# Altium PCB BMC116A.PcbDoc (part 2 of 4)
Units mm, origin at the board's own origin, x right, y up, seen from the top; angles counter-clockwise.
Board outline 154.94 x 104.14 mm, 6 copper layers (Top Layer, Signal Layer 1, Signal Layer 2, Signal Layer 3, Signal Layer 4, Bottom Layer), stack 1.56 mm thick; 252 components, 114 nets, 652 pads, 2530 vias.
Unrouted connection lines stored in the file: 13.
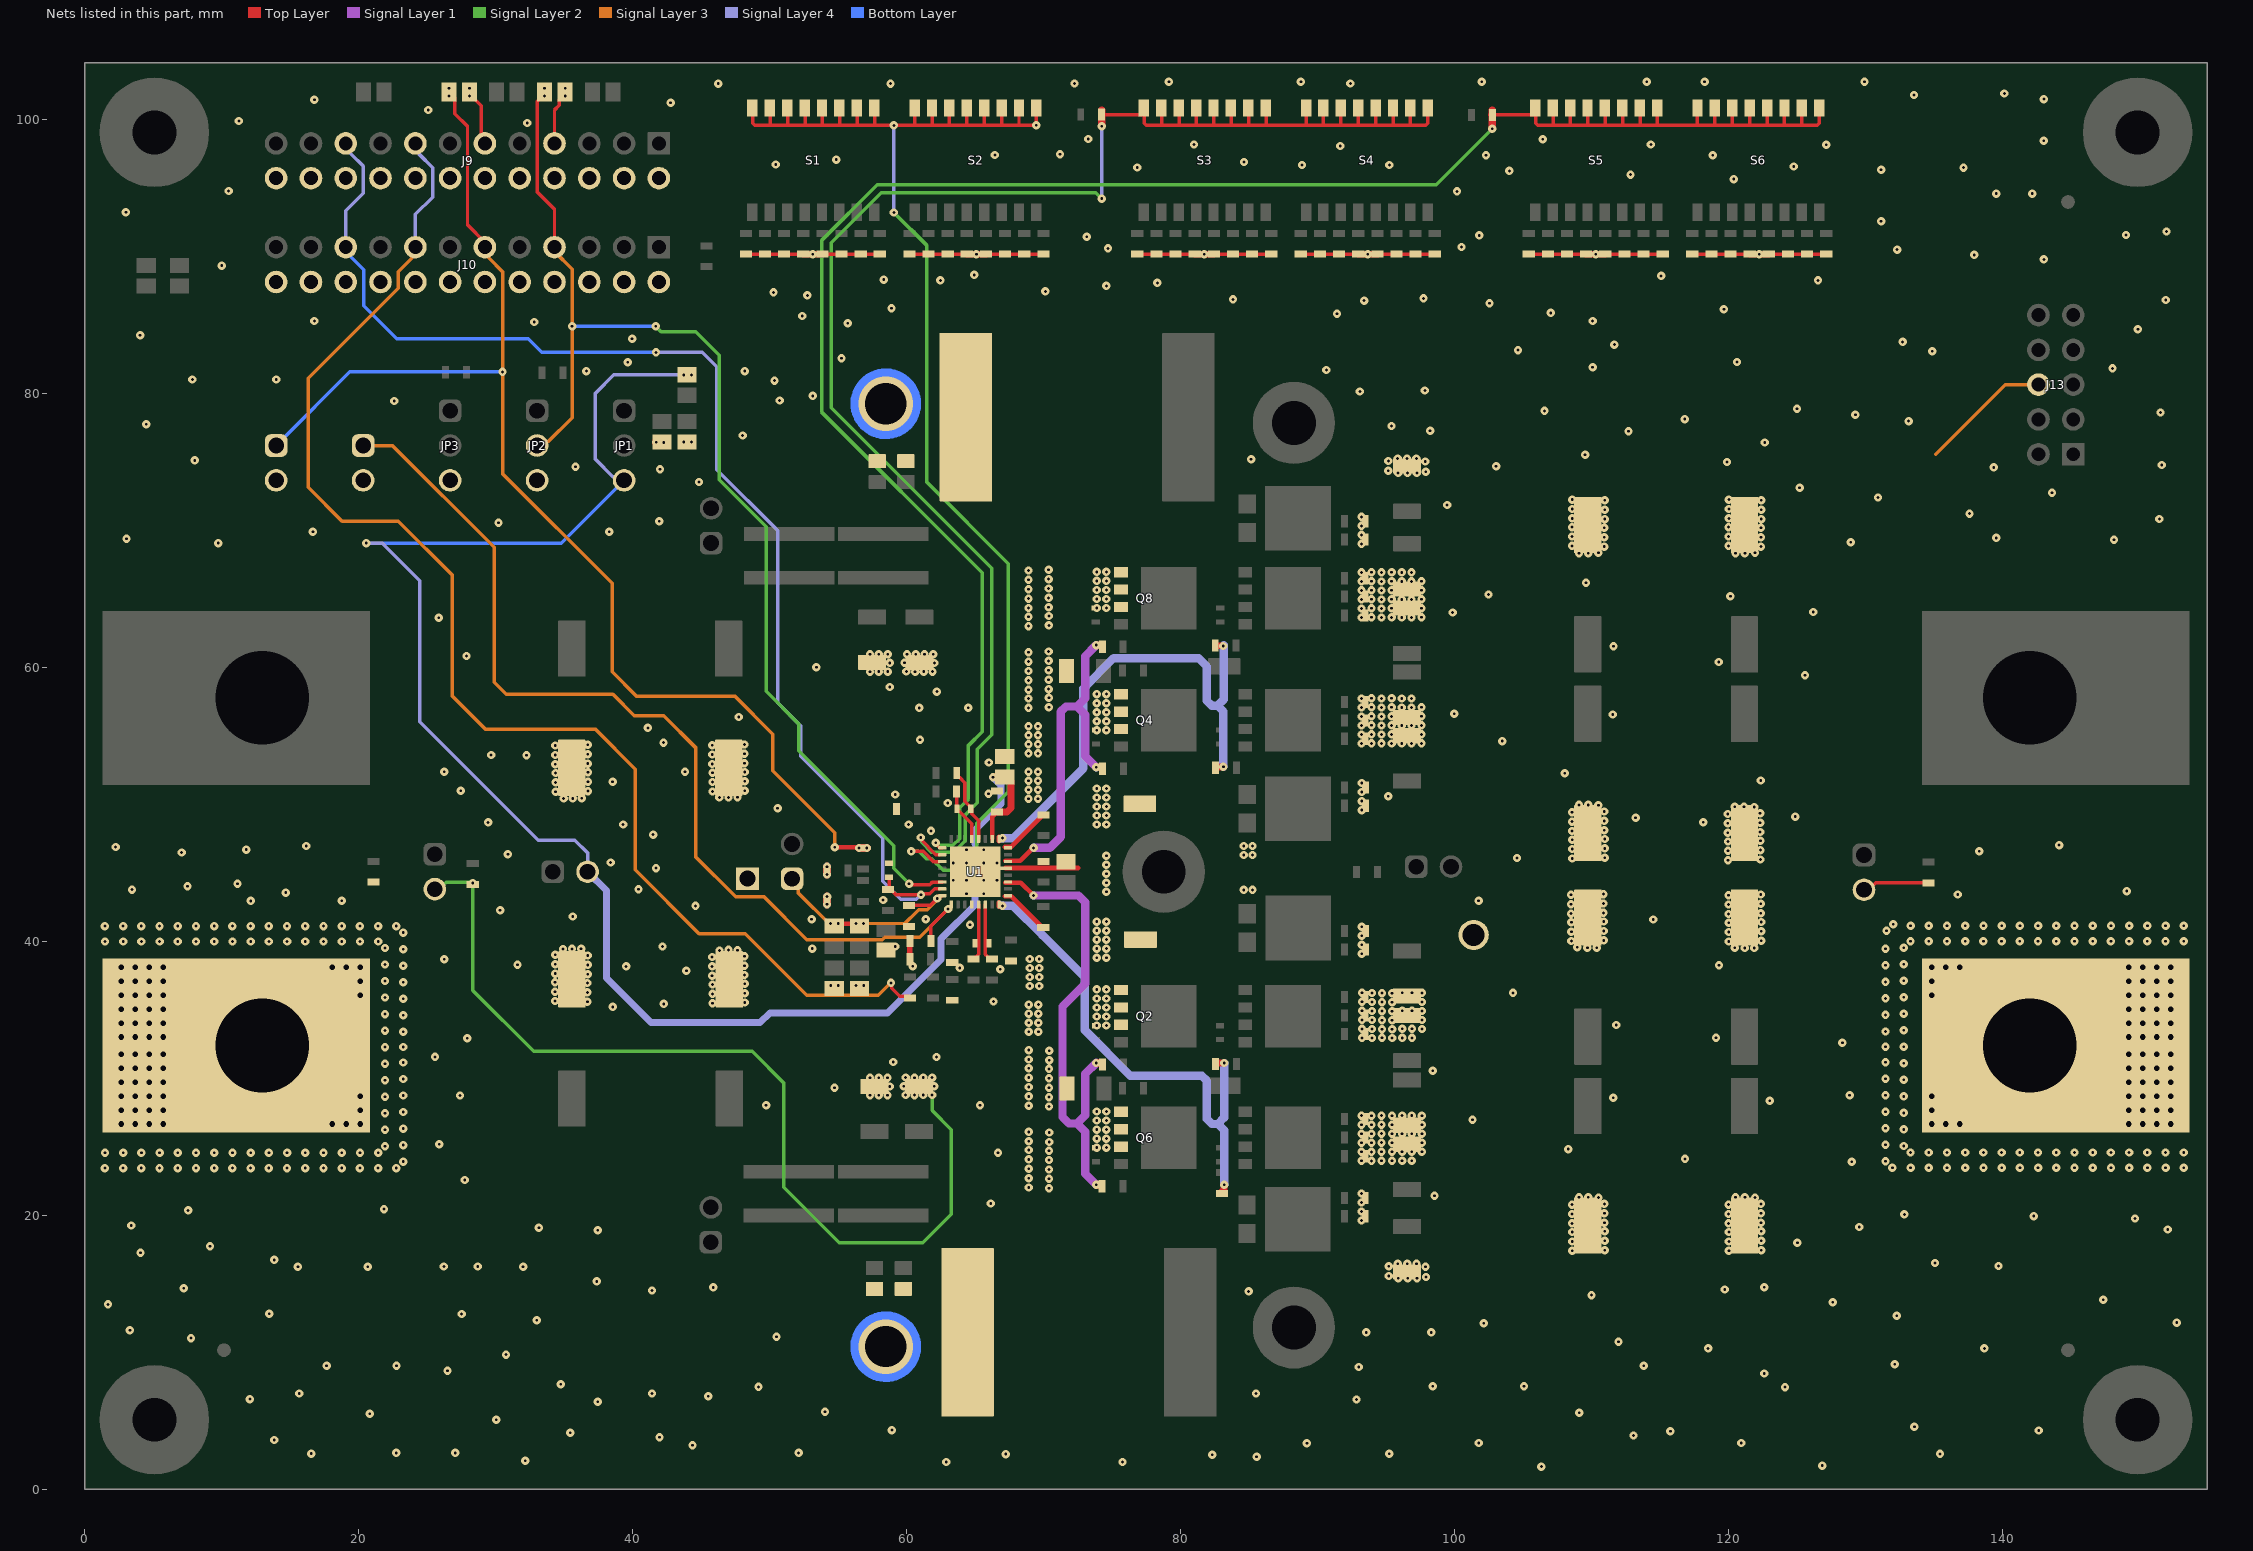
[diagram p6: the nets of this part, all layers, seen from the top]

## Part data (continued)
R31 R32 R33 R34 R35 R36 R37 R38: library part CMP-0025950-3, "RES, 100 k, 1%, 0.063 W, AEC-Q200 Grade 0, 0402", Manufacturer=Vishay-Dale, Power_W=63mW, Supplier Part Number 1=541-100KLCT-ND, TempCo="100 ppm/C", Tolerance_%=1%, Value2=0.063W, Value_Code=100k
R42 R58 R74: library part CMP-0022481-5, "RES, 511, 1%, 0.1 W, AEC-Q200 Grade 0, 0603", Manufacturer=Vishay-Dale, Power_W=100mW, Supplier Part Number 1=541-511HCT-ND, TempCo="100 ppm/C", Tolerance_%=1%, Value2=0.1W, Value_Code=511R, ValueDisplayed=511
R43 R59 R75: library part CMP-0022120-4, "RES, 1.30 k, 1%, 0.1 W, AEC-Q200 Grade 0, 0603", Manufacturer=Vishay-Dale, Power_W=100mW, Supplier Part Number 1=541-1.30KHCT-ND, TempCo="100 ppm/C", Tolerance_%=1%, Value2=0.1W, Value_Code=1k30, ValueDisplayed=1.30k
R44 R60 R76: library part CMP-0022135-4, "RES, 1.87 k, 1%, 0.1 W, AEC-Q200 Grade 0, 0603", Manufacturer=Vishay-Dale, Power_W=100mW, Supplier Part Number 1=541-1.87KHCT-ND, TempCo="100 ppm/C", Tolerance_%=1%, Value2=0.1W, Value_Code=1k87, ValueDisplayed=1.87k
R45 R61 R77: library part CMP-0022281-4, "RES, 2.74 k, 1%, 0.1 W, AEC-Q200 Grade 0, 0603", Manufacturer=Vishay-Dale, Power_W=100mW, Supplier Part Number 1=541-2.74KHCT-ND, TempCo="100 ppm/C", Tolerance_%=1%, Value2=0.1W, Value_Code=2k74, ValueDisplayed=2.74k
R46 R62 R78: library part CMP-0022381-4, "RES, 3.83 k, 1%, 0.1 W, AEC-Q200 Grade 0, 0603", Manufacturer=Vishay-Dale, Power_W=100mW, Supplier Part Number 1=541-3.83KHCT-ND, TempCo="100 ppm/C", Tolerance_%=1%, Value2=0.1W, Value_Code=3k83, ValueDisplayed=3.83k
R47 R63 R79: library part CMP-0022509-4, "RES, 5.11 k, 1%, 0.1 W, AEC-Q200 Grade 0, 0603", Manufacturer=Vishay-Dale, Power_W=100mW, Supplier Part Number 1=541-5.11KHCT-ND, TempCo="100 ppm/C", Tolerance_%=1%, Value2=0.1W, Value_Code=5k11, ValueDisplayed=5.11k
R48 R64 R80: library part CMP-0022561-4, "RES, 6.49 k, 1%, 0.1 W, AEC-Q200 Grade 0, 0603", Manufacturer=Vishay-Dale, Power_W=100mW, Supplier Part Number 1=541-6.49KHCT-ND, TempCo="100 ppm/C", Tolerance_%=1%, Value2=0.1W, Value_Code=6k49, ValueDisplayed=6.49k
R49 R65 R81: library part CMP-0022635-4, "RES, 8.25 k, 1%, 0.1 W, AEC-Q200 Grade 0, 0603", Manufacturer=Vishay-Dale, Power_W=100mW, Supplier Part Number 1=541-8.25KHCT-ND, TempCo="100 ppm/C", Tolerance_%=1%, Value2=0.1W, Value_Code=8k25, ValueDisplayed=8.25k
R50 R66 R82: library part CMP-0022000-4, "RES, 10.5 k, 1%, 0.1 W, AEC-Q200 Grade 0, 0603", Manufacturer=Vishay-Dale, Power_W=100mW, Supplier Part Number 1=541-10.5KHCT-ND, TempCo="100 ppm/C", Tolerance_%=1%, Value2=0.1W, Value_Code=10k5, ValueDisplayed=10.5k
R51 R67 R83: library part CMP-0022043-4, "RES, 13.3 k, 1%, 0.1 W, AEC-Q200 Grade 0, 0603", Manufacturer=Vishay-Dale, Power_W=100mW, Supplier Part Number 1=541-13.3KHCT-ND, TempCo="100 ppm/C", Tolerance_%=1%, Value2=0.1W, Value_Code=13k3, ValueDisplayed=13.3k
R52 R68 R84: library part CMP-0022079-4, "RES, 16.2 k, 1%, 0.1 W, AEC-Q200 Grade 0, 0603", Manufacturer=Vishay-Dale, Power_W=100mW, Supplier Part Number 1=541-16.2KHCT-ND, TempCo="100 ppm/C", Tolerance_%=1%, Value2=0.1W, Value_Code=16k2, ValueDisplayed=16.2k
R53 R69 R85: library part CMP-0022205-4, "RES, 20.5 k, 1%, 0.1 W, AEC-Q200 Grade 0, 0603", Manufacturer=Vishay-Dale, Power_W=100mW, Supplier Part Number 1=541-20.5KHCT-ND, TempCo="100 ppm/C", Tolerance_%=1%, Value2=0.1W, Value_Code=20k5, ValueDisplayed=20.5k
R54 R70 R86: library part CMP-0022237-4, "RES, 24.9 k, 1%, 0.1 W, AEC-Q200 Grade 0, 0603", Manufacturer=Vishay-Dale, Power_W=100mW, Supplier Part Number 1=541-24.9KHCT-ND, TempCo="100 ppm/C", Tolerance_%=1%, Value2=0.1W, Value_Code=24k9, ValueDisplayed=24.9k
R55 R71 R87: library part CMP-0022324-4, "RES, 30.1 k, 1%, 0.1 W, AEC-Q200 Grade 0, 0603", Manufacturer=Vishay-Dale, Power_W=100mW, Supplier Part Number 1=541-30.1KHCT-ND, TempCo="100 ppm/C", Tolerance_%=1%, Value2=0.1W, Value_Code=30k1, ValueDisplayed=30.1k
R56 R72 R88: library part CMP-0022356-4, "RES, 36.5 k, 1%, 0.1 W, AEC-Q200 Grade 0, 0603", Manufacturer=Vishay-Dale, Power_W=100mW, Supplier Part Number 1=541-36.5KHCT-ND, TempCo="100 ppm/C", Tolerance_%=1%, Value2=0.1W, Value_Code=36k5, ValueDisplayed=36.5k
R89 R90 R103 R104: library part CMP-0022458-4, "RES, 4.99 k, 1%, 0.1 W, AEC-Q200 Grade 0, 0603", Manufacturer=Vishay-Dale, Power_W=100mW, Supplier Part Number 1=541-4.99KHCT-ND, TempCo="100 ppm/C", Tolerance_%=1%, Value2=0.1W, Value_Code=4k99, ValueDisplayed=4.99k
R91 R92 R96 R97 R98 R99 R100: library part CMP-0020442-3, "RES, 0, 5%, 0.125 W, AEC-Q200 Grade 0, 0805", Manufacturer=Vishay-Dale, Power_W=125mW, Supplier Part Number 1=541-0.0ACT-ND, TempCo="200 ppm/C", Tolerance_%=5%, Value2=0.125W, Value_Code=0000, ValueDisplayed=0
R93: library part CMP-0021246-3, "RES, 40.2 k, 1%, 0.125 W, AEC-Q200 Grade 0, 0805", Manufacturer=Vishay-Dale, Power_W=125mW, Supplier Part Number 1=541-40.2KCCT-ND, TempCo="100 ppm/C", Tolerance_%=1%, Value2=0.125W, Value_Code=40k2, ValueDisplayed=40.2k
R95: library part CMP-0025874-4, "RES, 0, 5%, 0.1 W, AEC-Q200 Grade 0, 0603", Manufacturer=Panasonic, Power_W=100mW, Supplier Part Number 1=P0.0GCT-ND, TempCo="600 ppm/C", Tolerance_%=5%, Value2=0.1W, Value_Code=0000, ValueDisplayed=0
R101 R102: library part CMP-0020842-3, "RES, 10.0 k, 1%, 0.125 W, AEC-Q200 Grade 0, 0805", Manufacturer=Vishay-Dale, Power_W=125mW, Supplier Part Number 1=541-10.0KCCT-ND, TempCo="100 ppm/C", Tolerance_%=1%, Value2=0.125W, Value_Code=10k0, ValueDisplayed=10.0k
S1 S2 S3 S4 S5 S6: library part CMP-0002229-1, "Switch, SPST, 8 Pos, 25mA, 24VDC, SMD", CurrentRating_mA=25A, Manufacturer="CTS Electrocomponents", Supplier Part Number 1=CT2188LPST-ND
SH-JP1 SH-JP2 SH-JP3 SH-JP4 SH-JP5 SH-JP6: library part CMP-0003642-1, "Shunt, 100mil, Flash Gold, Black", Manufacturer="Sullins Connector Solutions", Supplier Part Number 1=S9001-ND
T1 T2 T3 T4: library part CMP-0075010-2, "Terminal 70A Lug", Manufacturer=Panduit, Supplier Part Number 1=CXS70-14-C-ND
TP1 TP2 TP3 TP4: library part CMP-0067620-1, "PC Test Point, SMT", Manufacturer="TE Connectivity", Supplier Part Number 1=A106145CT-ND
TP5: library part CMP-0055143-2, "Test Point, Compact, Black, TH", Color=Black, Manufacturer="Keystone Electronics", Supplier Part Number 1=36-5006-ND
U1: library part CMP-0120194-1, "Wide-VIN, 2.2 MHz dual-phase boost controller with VOUT tracking", Manufacturer="Texas Instruments", Max Supply Voltage=42V, Min Supply Voltage=2.5V, Nominal Supply Current=1500uA, Operating Temperature Range="-40°C to +125°C", Output Voltage=6-60V, Switching Frequency=100-2200kHz
ZZ2: library part CMP-0077236-1
ZZ3: library part CMP-0077237-1
ZZ4: library part CMP-0077238-1
ZZ5 ZZ6 ZZ7 ZZ8 ZZ9 ZZ10: library part CMP-0077238-1, "These assemblies must comply with workmanship standards IPC-A-610 Class 2, unless otherwise specified."

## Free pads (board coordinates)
  round 6 hole 3.2: 2(78.765,45.085) 2(88.265,11.811) 2(88.265,77.851)

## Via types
v1: diameter 0.61, hole 0.203, Top Layer to Bottom Layer, tented both sides, 2282 vias
v2: diameter 0.813, hole 0.406, Top Layer to Bottom Layer, 232 vias
v3: diameter 0.5, hole 0.2, Top Layer to Bottom Layer, tented both sides, 12 vias
v4: diameter 4, hole 3, Top Layer to Bottom Layer, 4 vias

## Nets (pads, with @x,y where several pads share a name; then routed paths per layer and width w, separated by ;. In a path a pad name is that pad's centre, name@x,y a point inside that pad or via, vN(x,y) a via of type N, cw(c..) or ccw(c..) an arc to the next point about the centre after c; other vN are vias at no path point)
AGND: C1.2 C2.1 C6.2 C7.2 C8.2 C15.2 C16.2 C17.2 C18.2 C19.2 C20.2 J7.2 J8.2 J9.2 J9.4 J9.6 J9.8 J9.10 J9.12 J9.14 J9.16 J9.18 J9.20 J9.22 J9.24 J10.2 J10.4 J10.6 J10.8 J10.10 J10.12 J10.14 J10.16 J10.18 J10.20 J10.22 J10.24 J13.6 J14.1 JP2.3 JP3.3 NT1.1 R5.1 R6.1 R7.1 R10.2 R41.2 R42.1 R43.2 R44.1 R45.2 R46.1 R47.1 R48.1 R49.1 R50.1 R51.1 R52.2 R53.1 R54.1 R55.1 R56.2 R57.2 R58.1 R59.2 R60.1 R61.2 R62.1 R63.1 R64.1 R65.1 R66.1 R67.1 R68.2 R69.1 R70.1 R71.1 R72.2 R73.2 R74.1 R75.2 R76.1 R77.2 R78.1 R79.1 R80.1 R81.1 R82.1 R83.1 R84.2 R85.1 R86.1 R87.1 R88.2 R91.1 R92.1 TP5.1 U1.4 U1.33 | length 73.4
  Top Layer w0.254: C20.2@41.553,76.574 41.821,76.574 C20.2@41.949,76.446 ; R41.2@48.26,90.17 R42.1@49.657,90.17 R43.2@51.054,90.17 R44.1@52.451,90.17 ; R45.2@53.848,90.17 R46.1@55.245,90.17 R47.1@56.642,90.17 R48.1@58.039,90.17 ; R49.1@60.198,90.17 R50.1@61.595,90.17 R51.1@62.992,90.17 R52.2@64.389,90.17 ; C8.2@60.228,38.693 C8.2@60.234,38.7 ; C7.2@60.234,40.02 C7.2@60.241,40.027 ; R53.1@65.786,90.17 R54.1@67.183,90.17 R55.1@68.58,90.17 R56.2@69.977,90.17 ; R57.2@76.835,90.17 R58.1@78.232,90.17 R59.2@79.629,90.17 R60.1@81.026,90.17 ; R61.2@82.423,90.17 R62.1@83.82,90.17 R63.1@85.217,90.17 R64.1@86.614,90.17 ; R65.1@88.773,90.17 R66.1@90.17,90.17 R67.1@91.567,90.17 R68.2@92.964,90.17 ; R69.1@94.361,90.17 R70.1@95.758,90.17 R71.1@97.155,90.17 R72.2@98.552,90.17 ; R73.2@105.41,90.17 R74.1@106.807,90.17 R75.2@108.204,90.17 R76.1@109.601,90.17 ; R77.2@110.998,90.17 R78.1@112.395,90.17 R79.1@113.792,90.17 R80.1@115.189,90.17 ; R81.1@117.348,90.17 R82.1@118.745,90.17 R83.1@120.142,90.17 R84.2@121.539,90.17 ; R85.1@122.936,90.17 R86.1@124.333,90.17 R87.1@125.73,90.17 R88.2@127.127,90.17
  Top Layer w0.406: C8.2@60.234,38.7 C7.2@60.234,40.02
  Top Layer w0.495: R44.1@52.451,90.17 R45.2@53.848,90.17 ; R52.2@64.389,90.17 R53.1@65.786,90.17 ; R60.1@81.026,90.17 R61.2@82.423,90.17 ; R68.2@92.964,90.17 R69.1@94.361,90.17 ; R76.1@109.601,90.17 R77.2@110.998,90.17 ; R84.2@121.539,90.17 R85.1@122.936,90.17
  Top Layer w0.61: v1(41.713,76.434) C20.2@42.267,76.434 ; v1(43.732,76.456) R10.2@44.285,76.456 ; v1(54.18,44.889) C19.2@54.18,45.443 ; v1(54.185,42.713) C18.2@54.185,43.267 ; R92.1@54.451,36.633 R92.1@55.004,36.633 ; R91.1@56.302,36.633 R91.1@56.856,36.633
  Signal Layer 3 w0.254: 135.128,75.565 140.208,80.645 J13.6@142.621,80.645
  other v1: 106.336,1.66 62.888,2 75.75,2 32.159,2.081 85.547,2.382 95.224,2.6 22.741,2.659 120.926,3.383 13.828,3.602 41.952,3.795 113.059,3.931 133.563,4.572 30.035,5.08 54.036,5.659 37.448,6.396 45.514,6.799 15.65,7 85.496,7 124.119,7.464 105.068,7.522 93.006,8.933 22.75,9.019 113.8,9.026 30.75,9.838 7.75,11.04 50.5,11.138 98.293,11.459 3.294,11.61 152.711,12.17 132.284,12.675 13.46,12.812 109.99,14.181 119.718,14.586 45.886,14.742 37.374,15.18 32,16.25 26.212,16.272 139.703,16.304 13.828,16.75 4.061,17.263 125.025,18.006 149.672,19.769 132.834,20.073 7.54,20.366 21.84,20.458 98.53,21.433 128.992,23.909 25.872,25.185 49.739,28.044 65.356,28.044 123.009,28.367 111.587,28.585 54.726,29.315 98.406,30.565 59.012,31.201 62.181,31.557 128.307,32.595 27.913,32.93 38.546,35.22 66.336,35.614 104.267,36.243 54.451,36.783 55.009,36.779 56.302,36.783 56.86,36.779 43.918,37.855 66.827,37.968 63.874,38.067 60.446,38.193 119.295,38.251 31.583,38.29 26.236,38.692 53.105,39.476 42.177,39.624 59.172,39.626 64.62,41.208 53.058,41.621 61.386,41.621 44.585,42.591 12.111,42.958 58.277,43.026 54.19,43.271 149.06,43.671 3.444,43.781 40.42,43.815 7.498,44.031 54.185,45.447 38.388,45.765 104.556,46.087 30.889,46.355 11.788,46.699 2.25,46.888 16.16,46.96 144.131,47.029 41.487,47.794 61.779,48.066 39.299,48.533 60.141,48.533 29.442,48.689 113.214,49.031 50.579,49.717 62.996,50.107 95.155,50.598 59.172,50.726 65.97,50.781 122.352,51.75 26.236,52.382 43.816,52.382 66.003,53.063 32.242,53.597 103.47,54.621 60.974,54.721 41.107,55.585 47.741,56.381 111.544,56.568 99.971,56.617 64.498,57.05 62.205,58.235 58.769,58.567 125.575,59.436 53.41,60.019 27.869,60.839 25.839,63.629 99.854,64.014 120.133,65.196 109.588,66.178 9.741,69.076 128.923,69.146 148.141,69.317 3.041,69.393 16.652,69.901 41.936,70.674 137.587,71.23 99.451,71.855 41.991,74.471 35.825,74.651 151.624,74.782 8.029,75.115 109.524,75.533 42.271,76.429 122.639,76.421 44.289,76.452 48.022,76.928 98.209,77.275 4.484,77.745 116.793,78.126 129.256,78.443 22.595,79.447 53.149,79.825 93.086,80.144 50.345,80.94 7.857,81.015 13.97,81.015 36.617,81.634 48.182,81.634 39.635,82.283 55.237,82.568 111.665,83.568 132.703,83.764 39.956,84 4.04,84.25 149.882,84.686 55.702,85.126 32.811,85.221 16.762,85.291 91.412,85.813 107.02,85.881 119.657,86.155 97.731,86.94 52.75,87.159 74.581,87.854 62.458,88.257 10,89.336 137.929,90.116 53.149,90.17 65.087,90.17 81.724,90.17 93.662,90.17 110.299,90.17 122.237,90.17 73.14,91.448 101.794,91.541 151.966,91.824 131.132,92.575 3,93.226 142.164,94.59 100.179,94.75 10.5,94.778 120.374,95.649 112.839,95.977 76.835,96.5 137.147,96.488 50.441,96.715 84.627,96.897 102.287,97.386 66.438,97.404 91.645,98.071 127.127,98.149 106.44,98.552 73.25,98.575 32.304,99.74 11.25,99.892 25.073,100.695 42.767,101.226 16.762,101.449 143.018,101.489 92.39,102.631 79.141,102.75 118.25,102.75 129.925,102.75
  other v3: 64.369,43.485 65.629,43.485 63.399,44.455 64.369,44.455 65.629,44.455 66.599,44.455 63.399,45.715 64.369,45.715 65.629,45.715 66.599,45.715 64.369,46.685 65.629,46.685
ATRK/DTRK: C17.1 JP5.1 R93.2 R94.2 U1.32 | length 17.8
  Top Layer w0.254: C17.1@60.177,42.49 C17.1@60.177,42.627 ; C17.1@60.586,42.627 61.725,42.627 v1(62.228,43.131) v1@62.228,43.135 ; U1.32@62.428,43.335 U1.32@62.599,43.335
  Top Layer w0.305: R94.2@54.995,41.283 R93.2@56.304,41.283
  Top Layer w0.406: v1@62.225,43.111 U1.32@62.369,43.255
  Top Layer w0.61: v1(54.447,41.31) R94.2@55,41.31 ; v1(56.298,41.31) R93.2@56.851,41.31
  Signal Layer 3 w0.254: JP5.1@51.636,44.571 52.069,44.138 52.069,43.564 v1@54.451,41.182 ; v1@54.623,41.246 v1@55.004,41.246 ; v1(55.004,41.306) v1@56.294,41.306 ; v1@56.302,41.193 56.315,41.18 56.847,41.18 v1@56.86,41.193 ; v1(56.856,41.306) 59.853,41.306 60.761,42.213 60.866,42.319 61.495,42.319 62.228,43.052 v1(62.228,43.131)
ATRK_EXT: J8.1 J10.11 R99.1 R104.2 | length 92.5
  Top Layer w0.254: R99.1@26.59,102 27.013,101.577 27.013,100.419 27.938,99.494 27.938,92.303 29.21,91.031 J10.11@29.21,90.678
  Top Layer w0.305: v1(54.742,46.868) R104.2@57.005,46.868 ; R104.2@56.759,46.868 R104.2@56.803,46.823
  Top Layer w0.61: v1(56.527,46.823) R104.2@57.08,46.823
  Signal Layer 3 w0.254: J10.11@29.477,90.411 29.477,89.91 30.495,88.892 v1(30.495,81.574) 30.495,74.144 38.497,66.142 38.497,59.674 40.259,57.912 47.442,57.912 50.22,55.134 50.22,52.453 54.742,47.93 v1(54.742,46.868)
  Signal Layer 4 w0.254: J10.11@29.21,90.678 J10.11@29.477,90.411
  Bottom Layer w0.254: J8.1@14,76.528 14.298,76.528 19.344,81.574 v1(30.495,81.574)
  other v1: 57.084,46.819 26.586,101.719 26.59,102.277
ATRK_EXT_SEC: J9.11 R99.2 | length 4.2
  Top Layer w0.254: R99.2@28.09,102 28.09,101.85 28.931,101.01 28.931,99.102 28.943,99.09 28.943,98.522 J9.11@29.21,98.255
  other v1: 28.086,101.719 28.09,102.277
BIAS: C1.1 C2.2 JP1.3 JP4.2 R9.1 U1.18 | length 126.6
  Top Layer w0.254: C2.2@67.16,51.991 C2.2@67.164,51.988
  Top Layer w0.33: U1.18@66.249,47.485 66.249,49.085 C1.1@66.442,49.279
  Top Layer w0.508: C1.1@66.599,49.455 67.313,49.455 67.611,49.753 67.611,51.691 67.314,51.988 C2.2@67.164,51.988
  Top Layer w0.559: v1@66.32,51.991 C2.2@67.16,51.991
  Top Layer w0.61: v1(43.732,81.356) R9.1@44.285,81.356
  Signal Layer 4 w0.254: v1(20.548,69.076) 21.704,69.076 24.464,66.317 24.464,56.041 33.112,47.393 35.767,47.393 36.703,46.457 JP4.2@36.703,45.085 ; JP1.3@39.103,73.927 38.553,73.927 37.281,75.2 37.281,80.025 38.612,81.356 v1(43.732,81.356)
  Signal Layer 4 w0.356: 64.999,43.137 64.999,47.201
  Signal Layer 4 w0.508: JP4.2@36.703,45.085 38.079,43.709 38.079,37.332 41.343,34.068 49.307,34.068 50.017,34.779 58.606,34.779 62.516,38.689 62.516,40.194 64.994,42.672 64.994,43.16 ; 64.982,47.122 64.982,48.131 66.885,50.035 66.885,50.841 66.885,51.399 v1(66.3,51.984)
  Bottom Layer w0.254: v1(20.548,69.076) 34.786,69.076 JP1.3@39.37,73.66 JP1.3@39.103,73.927
  other v1: 44.289,81.351
CFG0: S1.9 S1.10 S1.11 S1.12 S1.13 S1.14 S1.15 S1.16 S2.9 S2.10 S2.11 S2.12 S2.13 S2.14 S2.15 S2.16 U1.27 | length 107
  Top Layer w0.254: S1.16@48.768,100.838 48.768,99.717 48.917,99.568 50.038,99.568 ; S1.15@50.038,100.838 50.038,99.568 ; S1.14@51.308,100.838 51.308,99.568 ; 52.578,99.593 S1.13@52.578,100.858 ; 53.848,99.568 51.308,99.568 ; 53.848,99.588 S1.12@53.848,100.858 ; 53.873,99.568 55.093,99.568 ; S1.11@55.118,100.858 55.118,99.568 v1(59.067,99.568) 69.32,99.568 69.469,99.717 S2.9@69.469,100.838 ; 56.388,99.593 S1.10@56.388,100.858 ; 57.658,99.588 S1.9@57.658,100.858 ; v1@60.382,46.569 60.386,46.573 61.211,46.573 61.953,45.831 62.376,45.831 62.378,45.833 U1.27@62.426,45.833 ; 60.579,99.588 S2.16@60.579,100.838 S2.16@60.579,100.858 ; 61.849,99.588 S2.15@61.849,100.838 S2.15@61.849,100.858 ; 63.119,99.613 S2.14@63.119,100.838 S2.14@63.119,100.878 ; 64.389,99.608 S2.13@64.389,100.838 S2.13@64.389,100.878 ; 65.659,99.588 S2.12@65.659,100.838 S2.12@65.659,100.878 ; 66.929,99.613 S2.11@66.929,100.838 S2.11@66.929,100.878 ; 68.199,99.608 S2.10@68.199,100.838 S2.10@68.199,100.878 ; 50.038,99.568 51.308,99.568
  Signal Layer 2 w0.254: v1(59.067,93.211) 61.48,90.798 61.48,73.519 67.423,67.576 67.423,50.923 65.099,48.599 65.099,45.655 64.63,45.186 62.667,45.186 61.814,46.038 61.425,46.038 60.889,46.573 60.761,46.573 v1@60.386,46.573
  Signal Layer 4 w0.254: v1(59.067,93.211) v1(59.067,99.568)
  other v1: 60.335,46.569 69.455,99.574
CFG1: R39.2 S3.9 S3.10 S3.11 S3.12 S3.13 S3.14 S3.15 S3.16 S4.9 S4.10 S4.11 S4.12 S4.13 S4.14 S4.15 S4.16 U1.26 | length 126.9
  Top Layer w0.254: v1@61.052,47.413 62.129,46.335 U1.26@62.426,46.335 ; R39.2@74.371,100.338 S3.16@77.315,100.338 ; S3.16@77.343,100.838 77.343,99.717 77.492,99.568 82.423,99.568 97.895,99.568 98.044,99.717 S4.9@98.044,100.838 ; 78.613,99.588 S3.15@78.613,100.858 ; 79.883,99.588 S3.14@79.883,100.858 ; 81.153,99.613 S3.13@81.153,100.878 ; 82.423,99.608 S3.12@82.423,100.878 ; 83.693,99.588 S3.11@83.693,100.878 ; 84.963,99.613 S3.10@84.963,100.878 ; 86.233,99.608 S3.9@86.233,100.878 ; 89.154,99.588 S4.16@89.154,100.838 S4.16@89.154,100.858 ; 90.424,99.588 S4.15@90.424,100.838 S4.15@90.424,100.858 ; 91.694,99.613 S4.14@91.694,100.838 S4.14@91.694,100.878 ; 92.964,99.608 S4.13@92.964,100.838 S4.13@92.964,100.878 ; 94.234,99.588 S4.12@94.234,100.838 S4.12@94.234,100.878 ; 95.504,99.613 S4.11@95.504,100.838 S4.11@95.504,100.878 ; 96.774,99.608 S4.10@96.774,100.838 S4.10@96.774,100.878
  Top Layer w0.559: R39.2@74.23,100.358 74.234,100.354 74.234,99.506 v1(74.239,99.502) ; R39.2@74.235,100.363 R39.2@74.235,100.671
  Signal Layer 2 w0.254: v1@61.069,47.485 61.096,47.457 61.096,47.226 61.798,46.524 63.459,46.524 64.269,47.334 64.269,49.226 65.151,50.108 65.151,50.841 65.151,54.033 66.215,55.097 66.215,67.251 54.5,78.966 54.5,91.002 58.15,94.653 73.812,94.653 v1(74.239,94.225)
  Signal Layer 4 w0.254: v1(74.239,94.225) v1(74.239,99.502)
  other v1: 61.028,47.584
CFG2: R40.2 S5.9 S5.10 S5.11 S5.12 S5.13 S5.14 S5.15 S5.16 S6.9 S6.10 S6.11 S6.12 S6.13 S6.14 S6.15 S6.16 U1.25 | length 149.6
  Top Layer w0.254: v1@62.14,47.222 62.208,47.154 62.208,47.055 62.428,46.835 U1.25@62.599,46.835 ; R40.2@102.75,100.338 S5.16@105.89,100.338 ; S5.16@105.918,100.838 105.918,100.338 105.918,99.717 106.067,99.568 107.188,99.568 108.458,99.568 109.728,99.568 110.998,99.568 112.268,99.568 113.538,99.568 114.808,99.568 116.268,99.568 117.729,99.568 118.999,99.568 120.269,99.568 121.539,99.568 122.809,99.568 124.079,99.568 125.349,99.568 126.47,99.568 126.619,99.717 S6.9@126.619,100.838 ; 107.188,99.588 S5.15@107.188,100.858 ; 108.458,99.588 S5.14@108.458,100.858 ; 109.728,99.613 S5.13@109.728,100.878 ; 110.998,99.608 S5.12@110.998,100.878 ; 112.268,99.588 S5.11@112.268,100.878 ; 113.538,99.613 S5.10@113.538,100.878 ; 114.808,99.608 S5.9@114.808,100.878 ; 117.729,99.588 S6.16@117.729,100.838 S6.16@117.729,100.858 ; 118.999,99.588 S6.15@118.999,100.838 S6.15@118.999,100.858 ; 120.269,99.613 S6.14@120.269,100.838 S6.14@120.269,100.878 ; 121.539,99.608 S6.13@121.539,100.838 S6.13@121.539,100.878 ; 122.809,99.588 S6.12@122.809,100.838 S6.12@122.809,100.878 ; 124.079,99.613 S6.11@124.079,100.838 S6.11@124.079,100.878 ; 125.349,99.608 S6.10@125.349,100.838 S6.10@125.349,100.878
  Top Layer w0.559: R40.2@102.733,100.338 102.74,100.331 v1(102.74,99.322) ; R40.2@102.75,100.338 R40.2@102.751,100.67
  Signal Layer 2 w0.254: v1@62.14,47.222 62.192,47.222 62.404,47.01 63.37,47.01 63.863,47.502 63.863,49.752 64.509,50.398 64.509,50.841 64.509,54.305 65.518,55.314 65.518,66.914 53.782,78.65 53.782,91.167 57.861,95.246 98.664,95.246 v1(102.74,99.322)
  other v1: 62.115,47.203
COMP: J9.15 J10.15 R95.1 | length 99.4
  Top Layer w0.254: v1@58.839,37.165 58.907,37.097 58.907,36.575 59.479,36.002 60.116,36.002 R95.1@60.243,35.875
  Signal Layer 3 w0.254: J10.15@23.863,90.411 23.863,89.862 22.876,88.875 22.876,87.689 16.306,81.119 16.306,73.146 18.779,70.674 22.889,70.674 26.842,66.721 26.842,57.89 29.258,55.473 37.287,55.473 40.182,52.578 40.182,45.221 44.84,40.563 48.207,40.563 52.692,36.078 57.936,36.078 v1@58.829,36.971
  Signal Layer 4 w0.254: J10.15@23.863,90.411 J10.15@24.13,90.678 24.13,93.069 25.396,94.336 25.396,96.482 24.397,97.482 24.397,97.988 J9.15@24.13,98.255
  other v1: 58.858,36.971
CSN1: C11.2 R16.1 U1.5 | length 4.4
  Top Layer w0.254: R16.1@64.888,38.713 65.249,39.074 65.249,40.452 U1.5@65.249,42.685 ; C11.2@64.984,39.861 65.235,39.861
CSN2: C12.1 R18.1 U1.21 | length 3.9
  Top Layer w0.254: R18.1@63.65,50.947 63.65,50.841 63.65,49.678 64.749,48.58 U1.21@64.749,47.485
CSP1: C11.1 R15.1 U1.6 | length 4.6
  Top Layer w0.254: U1.6@65.749,42.685 65.749,40.452 65.749,39.861 ; C11.1@65.936,40.039 C11.1@66,39.975 ; C11.1@66,39.861 65.749,39.861 ; R15.1@66.228,38.684 66.072,38.684 65.916,38.84 65.916,38.876 65.749,39.043 65.749,39.861
CSP2: C12.2 R17.1 U1.20 | length 5.5
  Top Layer w0.254: R17.1@63.655,52.3 63.655,52.11 63.782,51.983 63.852,51.983 64.249,51.587 64.249,50.841 64.249,50.22 64.596,49.873 64.62,49.873 64.683,49.81 C12.2@64.683,49.696 64.747,49.632 64.747,49.306 65.249,48.803 U1.20@65.249,47.486
DLY: C7.1 J7.1 U1.1 | length 72.2
  Top Layer w0.254: C7.1@61.765,40.027 61.765,40.452 61.765,41.111 v1(63.023,42.37) 63.104,42.37 U1.1@63.247,42.512
  Signal Layer 3 w0.254: J7.1@20.32,76.2 22.448,76.2 29.889,68.76 29.889,58.912 30.761,58.039 38.561,58.039 40.123,56.477 42.266,56.477 44.585,54.159 44.585,46.188 47.512,43.26 49.584,43.26 52.715,40.13 58.227,40.13 58.405,40.308 60.962,40.308 61.106,40.452 v1(63.023,42.37)
EN2: J10.7 JP2.2 R97.1 U1.30 | length 87.7
  Top Layer w0.254: v1(33.552,101.72) 33.429,101.72 33.013,101.305 33.013,94.716 34.29,93.44 J10.7@34.29,90.678 ; v1(60.177,44.21) 60.243,44.145 61.695,44.145 61.883,44.333 62.597,44.333 U1.30@62.599,44.335
  Top Layer w0.61: R97.1@33.557,101.724 v1(33.557,102.278)
  Signal Layer 2 w0.254: v1(41.677,84.904) 42.065,84.516 44.604,84.516 46.328,82.792 46.328,73.705 49.75,70.283 49.75,58.257 52.134,55.873 52.134,53.904 59.053,46.985 59.053,45.334 v1(60.177,44.21)
  Signal Layer 3 w0.254: JP2.2@33.168,76.258 33.377,76.467 33.813,76.467 35.573,78.228 v1(35.573,84.904) 35.584,84.915 35.584,89.068 34.29,90.362 J10.7@34.29,90.678
  Bottom Layer w0.254: v1(35.573,84.904) v1(41.677,84.904)
  Bottom Layer w0.61: v1@33.557,101.724 v1(33.557,102.278)
EN2_SEC: J9.7 R97.2 | length 5
  Top Layer w0.254: J9.7@34.29,98.255 34.29,100.695 34.649,101.054 34.649,101.427 34.942,101.72 v1(35.076,101.72)
  Top Layer w0.61: R97.2@35.081,101.724 v1(35.081,102.278)
  Bottom Layer w0.61: v1@35.081,101.724 v1(35.081,102.278)
GND: C3.2 C4.2 C21.1 C22.1 C23.1 C24.1 C25.1 C26.1 C27.1 C28.1 C29.2 C30.2 C31.1 C32.1 C33.1 C34.1 C35.1 C36.1 C37.1 C38.1 C39.1 C40.1 C41.2 C42.2 C43.2 C44.2 C45.2 C46.2 C47.2 C48.2 C49.2 C50.2 C51.2 C52.2 C53.2 C54.2 C55.2 C56.2 C57.2 C58.2 C59.2 C60.2 C61.1 C62.1 C63.1 C64.1 C65.1 C66.1 C67.1 C68.1 C69.2 J2.1 J4.1 J5.2 J6.2 NT1.2 Q2.1 Q2.2 Q2.3 Q4.1 Q4.2 Q4.3 Q6.1 Q6.2 Q6.3 Q8.1 Q8.2 Q8.3 R29.1 R30.1 R32.1 R34.1 R36.1 R38.1 T2.1 T4.1 TP3.1 TP4.1 U1.13 | length 79.4
  Top Layer w0.254: J6.2@129.87,43.863 130.262,43.863 130.357,43.863 130.262,43.768 J6.2@129.885,43.768 130.231,43.768 130.342,43.879 130.731,44.268 C69.2@134.6,44.268
  Top Layer w0.343: U1.13@67.213,45.363 68.204,45.363
  Top Layer w0.381: 68.168,45.361 71.622,45.361 72.486,45.361
  Signal Layer 2 w0.254: J5.2@25.915,43.866 25.936,43.866 26.399,44.328 28.327,44.328 28.327,36.417 32.774,31.97 48.72,31.97 51.025,29.665 51.025,22.048 55.08,17.993 61.169,17.993 63.267,20.09 63.267,26.245 61.854,27.658 v1(61.854,28.786)
  Signal Layer 4 w0.254: J5.2@25.176,43.563 25.513,43.563 J5.2@25.513,43.613 ; v1@61.207,28.942 v1@61.271,28.878
  other v1: 126.84,1.73 82.307,2.526 67.236,2.57 135.436,2.589 16.535,2.607 27.043,2.659 52.108,2.659 44.368,3.222 89.213,3.362 101.756,3.383 35.437,4.134 115.753,4.239 142.648,4.3 58.919,4.322 20.802,5.524 109.091,5.584 92.832,6.562 12.054,6.587 41.405,7 49.186,7.477 98.406,7.522 34.75,7.67 122.6,8.457 26.479,8.656 17.652,9.019 132.135,9.129 118.504,10.29 138.675,10.29 111.964,10.779 93.543,11.459 102.123,12.124 32.989,12.346 27.506,12.8 1.698,13.5 127.612,13.652 147.355,13.835 84.963,14.452 41.405,14.517 7.23,14.681 122.599,14.752 95.886,15.412 96.572,15.412 97.258,15.412 97.911,15.506 95.196,15.577 15.558,16.25 20.663,16.25 97.874,16.249 28.687,16.272 95.196,16.279 95.849,16.463 96.535,16.463 97.221,16.463 135.069,16.525 108.592,17.409 120.021,17.409 110.956,17.461 122.385,17.461 9.141,17.75 108.592,18.095 120.021,18.095 110.956,18.147 122.385,18.147 108.592,18.781 120.021,18.781 110.956,18.833 122.385,18.833 37.448,18.907 152.062,18.97 33.148,19.096 129.535,19.153 3.387,19.259 108.568,19.416 119.997,19.416 110.931,19.468 122.36,19.468 93.199,19.621 142.282,19.948 108.568,20.102 119.997,20.102 110.931,20.154 122.36,20.154 93.199,20.28 108.568,20.788 119.997,20.788 110.931,20.839 122.36,20.839 66.143,20.866 93.199,20.938 110.498,21.295 121.927,21.295 109.076,21.32 109.762,21.32 120.505,21.32 121.191,21.32 93.199,21.597 70.387,21.98 68.916,22.031 27.743,22.579 70.387,22.666 68.916,22.717 70.387,23.352 68.916,23.403 1.466,23.448 2.796,23.448 4.125,23.448 5.455,23.448 6.785,23.448 8.115,23.448 9.444,23.448 10.774,23.448 12.104,23.448 13.433,23.448 14.763,23.448 16.093,23.448 17.422,23.448 18.752,23.448 20.082,23.448 21.412,23.448 22.741,23.448 131.96,23.471 133.29,23.471 134.62,23.471 135.949,23.471 137.279,23.471 138.609,23.471 139.938,23.471 141.268,23.471 142.598,23.471 143.927,23.471 145.257,23.471 146.587,23.471 147.916,23.471 149.246,23.471 150.576,23.471 151.906,23.471 153.235,23.471 23.241,23.923 131.46,23.947 93.199,23.989 93.933,23.978 95.425,23.981 94.666,23.992 96.167,23.991 96.876,23.991 70.387,24.038 68.916,24.088 116.816,24.124 1.473,24.569 2.803,24.569 4.132,24.569 5.462,24.569 6.792,24.569 8.121,24.569 9.451,24.569 10.781,24.569 12.111,24.569 13.44,24.569 14.77,24.569 16.1,24.569 17.429,24.569 18.759,24.569 20.089,24.569 21.418,24.569 66.669,24.564 133.283,24.593 134.613,24.593 135.942,24.593 137.272,24.593 138.602,24.593 139.931,24.593 141.261,24.593 142.591,24.593 143.921,24.593 145.25,24.593 146.58,24.593 147.91,24.593 149.239,24.593 150.569,24.593 151.899,24.593 153.228,24.593 93.199,24.647 93.933,24.636 94.666,24.651 95.425,24.64 96.167,24.649 96.876,24.649 97.609,24.638 70.387,24.723 68.916,24.774 108.289,24.835 73.882,24.945 74.581,24.945 21.918,25.045 132.783,25.068 23.241,25.129 131.46,25.153 93.199,25.306 93.933,25.295 94.666,25.309 95.425,25.298 97.609,25.297 70.411,25.358 68.916,25.409 73.882,25.603 74.581,25.603 93.199,25.964 93.933,25.953 94.666,25.968 95.425,25.957 96.167,25.966 96.876,25.966 97.609,25.955 70.411,26.044 68.916,26.095 21.918,26.251 73.882,26.262 74.581,26.262 132.783,26.275 23.241,26.335 131.46,26.359 93.199,26.623 93.933,26.612 94.666,26.626 95.425,26.615 97.609,26.614 73.882,26.92 74.581,26.92 101.302,26.977 93.199,27.281 93.933,27.27 94.666,27.285 95.425,27.274 96.167,27.283 96.876,27.283 97.609,27.272 21.918,27.457 132.783,27.481 23.241,27.542 131.46,27.565 73.882,27.579 74.581,27.579 70.387,27.949 68.916,28 70.387,28.635 21.918,28.663 68.916,28.686 132.783,28.687 23.241,28.748 27.386,28.748 57.316,28.768 57.953,28.776 58.6,28.772 59.923,28.79 60.57,28.782 61.207,28.789 128.834,28.771 131.46,28.771 70.387,29.321 68.916,29.372 58.758,29.409 62.011,29.423 59.778,29.427 21.918,29.869 132.783,29.893 23.241,29.954 131.46,29.977 70.387,30.007 57.316,30.04 57.953,30.048 58.6,30.044 60.57,30.054 61.854,30.058 68.916,30.057 59.923,30.062 61.207,30.061 70.387,30.692 68.916,30.743 21.918,31.075 132.783,31.099 23.241,31.16 131.46,31.183 70.411,31.327 68.916,31.378 25.568,31.567 70.411,32.013 68.916,32.064 21.918,32.282 23.247,32.293 131.46,32.305 132.783,32.305 93.234,32.955 93.968,32.944 95.435,32.948 94.701,32.959 96.176,32.957 96.885,32.957 119.077,32.959 23.241,33.403 68.916,33.409 69.614,33.409 131.46,33.427 21.918,33.488 132.783,33.511 95.435,33.581 93.234,33.614 93.968,33.603 94.701,33.592 96.176,33.616 96.885,33.616 97.619,33.605 73.882,33.86 74.581,33.86 111.805,33.902 68.916,34.068 69.614,34.068 94.701,34.25 95.435,34.24 93.234,34.272 93.968,34.261 97.619,34.263 73.882,34.519 74.581,34.519 23.241,34.609 131.46,34.633 21.918,34.694 68.916,34.727 69.614,34.727 132.783,34.717 94.701,34.909 95.435,34.898 93.234,34.931 93.968,34.92 96.176,34.933 96.885,34.933 97.619,34.922 73.882,35.177 74.581,35.177 68.916,35.385 69.614,35.385 42.271,35.438 45.819,35.484 48.182,35.536 94.701,35.567 95.435,35.557 36.69,35.592 93.234,35.589 93.968,35.578 97.619,35.58 34.327,35.644 23.241,35.816 73.882,35.836 74.581,35.836 131.46,35.839 21.918,35.9 132.783,35.923 45.819,36.17 48.182,36.222 94.701,36.226 95.435,36.215 93.234,36.248 93.968,36.237 96.176,36.25 96.885,36.25 97.619,36.239 36.69,36.278 34.327,36.33 73.882,36.494 74.581,36.494 68.984,36.743 69.682,36.743 45.819,36.856 48.182,36.908 36.69,36.964 34.327,37.015 23.241,37.022 131.46,37.045 21.918,37.106 132.783,37.13 68.984,37.402 69.682,37.402 45.794,37.491 48.158,37.543 36.715,37.599 34.351,37.65 68.984,38.06 69.682,38.06 39.517,38.177 45.794,38.177 23.241,38.228 48.158,38.229 131.46,38.251 36.715,38.284 21.918,38.312 34.351,38.336 132.783,38.336 68.984,38.719 69.682,38.719 73.881,38.813 74.58,38.813 45.794,38.863 48.158,38.914 36.715,38.97 34.351,39.022 93.215,39.099 46.331,39.335 46.991,39.381 47.652,39.36 23.241,39.434 34.913,39.445 35.57,39.452 131.46,39.457 36.234,39.469 73.881,39.472 74.58,39.472 21.918,39.518 121.183,39.517 121.869,39.517 109.694,39.544 110.38,39.544 120.446,39.542 132.783,39.542 108.958,39.569 93.215,39.758 1.473,39.994 2.803,39.994 4.132,39.994 5.462,39.994 6.792,39.994 8.121,39.994 9.451,39.994 10.781,39.994 12.111,39.994 13.44,39.994 14.77,39.994 16.1,39.994 17.429,39.994 18.759,39.994 20.089,39.994 21.418,39.994 120.014,39.998 133.283,40.017 134.613,40.017 135.942,40.017 137.272,40.017 138.602,40.017 139.931,40.017 141.261,40.017 142.591,40.017 143.921,40.017 145.25,40.017 146.58,40.017 147.91,40.017 149.239,40.017 150.569,40.017 151.899,40.017 153.228,40.017 108.525,40.024 122.377,40.049 110.888,40.076 73.881,40.13 74.58,40.13 93.215,40.416 23.241,40.64 120.014,40.683 108.525,40.71 122.377,40.735 110.888,40.762 131.527,40.778 73.881,40.789 74.58,40.789 93.215,41.075 1.466,41.116 2.796,41.116 4.125,41.116 5.455,41.116 6.785,41.116 8.115,41.116 9.444,41.116 10.774,41.116 12.104,41.116 13.433,41.116 14.763,41.116 16.093,41.116 17.422,41.116 18.752,41.116 20.082,41.116 21.412,41.116 22.741,41.116 133.29,41.139 134.62,41.139 135.949,41.139 137.279,41.139 138.609,41.139 139.938,41.139 141.268,41.139 142.598,41.139 143.927,41.139 145.257,41.139 146.587,41.139 147.916,41.139 149.246,41.139 150.576,41.139 151.906,41.139 153.235,41.139 132.014,41.254 120.014,41.369 108.525,41.396 122.377,41.421 73.881,41.447 74.58,41.447 110.888,41.448 114.5,41.602 35.628,41.822 119.989,42.004 108.5,42.031 122.352,42.056 110.864,42.083 30.319,42.276 119.989,42.69 108.5,42.717 122.352,42.742 110.864,42.768 18.76,42.962 101.75,42.968 119.989,43.376 108.5,43.402 136.726,43.421 122.352,43.428 110.864,43.454 14.671,43.563 74.58,43.626 84.604,43.76 85.244,43.76 11.145,44.208 28.324,44.269 74.58,44.284 74.58,44.943 41.701,45.35 74.58,45.601 119.961,45.925 122.324,45.977 108.591,46.055 110.955,46.107 74.58,46.26 84.604,46.305 85.244,46.305 7.066,46.486 138.307,46.582 119.961,46.611 122.324,46.663 108.591,46.741 110.955,46.792 84.604,46.964 85.244,46.964 119.961,47.297 122.324,47.349 108.591,47.426 110.955,47.478 119.936,47.932 122.299,47.984 108.567,48.061 110.93,48.113 73.881,48.533 74.58,48.533 119.936,48.618 122.299,48.669 118.155,48.701 108.567,48.747 110.93,48.799 124.862,49.109 73.881,49.191 74.58,49.191 119.936,49.303 122.299,49.355 108.567,49.433 110.93,49.485 93.215,49.584 121.867,49.81 120.444,49.836 121.13,49.836 73.881,49.85 74.58,49.85 110.497,49.94 109.075,49.965 109.761,49.965 93.215,50.243 68.887,50.406 69.586,50.406 34.956,50.432 35.62,50.44 36.277,50.456 46.328,50.501 46.996,50.502 47.649,50.526 73.881,50.508 74.58,50.508 93.215,50.902 34.372,50.92 45.822,50.947 36.736,50.972 27.44,50.999 48.186,50.999 68.887,51.065 69.586,51.065 73.881,51.167 74.58,51.167 93.215,51.56 34.372,51.606 45.822,51.633 36.736,51.658 38.53,51.659 48.186,51.685 68.887,51.723 69.586,51.723 108.034,52.271 34.372,52.292 45.822,52.319 36.736,52.343 48.186,52.37 68.887,52.382 69.586,52.382 34.348,52.927 45.798,52.954 36.711,52.978 48.161,53.005 29.66,53.612 34.348,53.612 45.798,53.639 36.711,53.664 48.161,53.691 68.887,53.727 69.586,53.727 34.348,54.298 45.798,54.325 36.711,54.35 48.161,54.377 68.887,54.386 69.586,54.386 93.199,54.445 96.141,54.443 96.85,54.443 93.933,54.456 94.665,54.453 95.4,54.452 97.584,54.454 42.244,54.511 68.887,55.044 69.586,55.044 93.199,55.103 94.666,55.1 93.933,55.114 95.4,55.111 97.584,55.112 73.881,55.417 74.58,55.417 68.887,55.703 69.586,55.703 93.199,55.762 94.666,55.758 96.141,55.76 96.85,55.76 93.933,55.773 95.4,55.769 97.584,55.771 73.881,56.075 74.58,56.075 93.199,56.42 94.666,56.417 93.933,56.431 95.4,56.428 97.584,56.429 73.881,56.734 74.58,56.734 60.91,57.048 68.887,57.048 93.199,57.079 94.666,57.075 95.4,57.086 96.141,57.077 96.85,57.077 70.382,57.099 93.933,57.09 97.584,57.088 73.881,57.392 74.58,57.392 68.887,57.734 93.199,57.737 94.666,57.734 95.4,57.745 96.141,57.735 96.85,57.735 93.933,57.748 70.382,57.785 73.881,58.051 74.58,58.051 68.887,58.369 70.358,58.42 68.887,59.055 70.358,59.106 57.326,59.69 57.962,59.697 58.61,59.694 59.98,59.698 60.615,59.69 61.252,59.697 61.886,59.694 68.887,59.741 70.358,59.792 58.767,60.331 59.836,60.335 62.023,60.328 119.281,60.394 68.887,60.427 70.358,60.477 57.326,60.962 57.962,60.969 58.61,60.966 60.027,60.969 60.662,60.961 61.299,60.968 61.937,60.966 68.887,61.112 70.358,61.163 111.603,61.552 68.887,63.017 70.382,63.068 93.199,63.648 93.933,63.659 94.666,63.644 95.4,63.655 96.141,63.646 96.85,63.646 97.584,63.657 68.887,63.703 70.382,63.754 126.188,64.051 93.199,64.307 93.933,64.317 94.666,64.303 95.4,64.314 97.584,64.315 68.887,64.338 73.882,64.34 74.581,64.34 70.358,64.389 93.199,64.965 93.933,64.976 94.666,64.962 95.4,64.972 96.141,64.963 96.85,64.963 97.584,64.974 73.882,64.999 74.581,64.999 68.887,65.024 70.358,65.075 102.475,65.326 94.666,65.62 93.199,65.624 93.933,65.635 95.4,65.631 97.584,65.633 73.882,65.657 74.581,65.657 68.887,65.71 70.358,65.761 94.666,66.279 96.141,66.28 96.85,66.28 93.199,66.282 93.933,66.293 95.4,66.289 97.584,66.291 73.882,66.316 74.581,66.316 68.887,66.396 70.358,66.446 93.199,66.941 94.666,66.937 96.141,66.939 96.85,66.939 93.933,66.952 95.4,66.948 73.882,66.974 74.581,66.974 68.887,67.081 70.358,67.132 109.075,68.342 109.761,68.342 120.505,68.342 121.191,68.342 110.497,68.367 121.927,68.367 110.93,68.823 122.36,68.823 108.567,68.874 119.997,68.874 93.199,69.017 139.546,69.457 110.93,69.508 122.36,69.508 108.567,69.56 119.997,69.56 93.199,69.675 38.283,69.901 110.93,70.194 122.36,70.194 108.567,70.246 119.997,70.246 93.199,70.334 30.197,70.565 110.955,70.829 122.385,70.829 151.449,70.832 108.591,70.881 120.021,70.881 93.199,70.992 110.955,71.515 122.385,71.515 108.591,71.567 120.021,71.567 110.955,72.201 122.385,72.201 108.591,72.253 120.021,72.253 130.905,72.403 143.607,72.75 125.185,73.11 44.836,73.537 95.874,74.199 96.56,74.199 97.246,74.199 97.899,74.293 95.159,74.364 139.35,74.603 103.031,74.682 119.882,74.996 97.862,75.036 95.165,75.072 85.142,75.192 95.837,75.249 96.523,75.249 97.209,75.249 112.694,77.235 95.394,77.628 133.144,77.981 151.527,78.61 106.566,78.728 124.989,78.885 50.721,79.489 97.83,80.22 90.641,81.713 148.031,81.831 110.075,81.915 120.613,82.302 134.872,83.088 104.625,83.166 110.075,85.287 52.38,85.652 58.894,86.214 102.544,86.584 93.391,86.78 151.92,86.819 83.82,86.867 50.28,87.377 70.125,87.454 78.301,88.072 126.525,88.253 58.321,88.31 115.073,88.582 64.936,88.657 143.018,89.787 132.3,90.5 74.693,90.591 100.5,90.696 149.013,91.573 139.546,94.59 104,96.25 131.132,96.326 124.75,96.564 88.862,96.679 95.237,96.679 54.856,97.072 118.845,97.386 71.197,97.465 80.978,98.172 114.328,98.172 143.003,98.447 133.536,101.786 140.136,101.903 46.25,102.622 58.823,102.622 72.25,102.631 88.776,102.75 101.974,102.75 114.023,102.75
  other v2: 2.667,26.67 3.683,26.67 4.699,26.67 5.715,26.67 18.066,26.67 19.082,26.67 20.098,26.67 134.842,26.67 135.858,26.67 136.874,26.67 149.225,26.67 150.241,26.67 151.257,26.67 152.273,26.67 2.667,27.686 3.683,27.686 4.699,27.686 5.715,27.686 20.098,27.686 134.842,27.686 149.225,27.686 150.241,27.686 151.257,27.686 152.273,27.686 2.667,28.702 3.683,28.702 4.699,28.702 5.715,28.702 20.098,28.702 134.842,28.702 149.225,28.702 150.241,28.702 151.257,28.702 152.273,28.702 2.667,29.718 3.683,29.718 4.699,29.718 5.715,29.718 149.225,29.718 150.241,29.718 151.257,29.718 152.273,29.718 2.667,30.734 3.683,30.734 4.699,30.734 5.715,30.734 149.225,30.734 150.241,30.734 151.257,30.734 152.273,30.734 2.667,31.75 3.683,31.75 4.699,31.75 5.715,31.75 149.225,31.75 150.241,31.75 151.257,31.75 152.273,31.75 2.667,33.02 3.683,33.02 4.699,33.02 5.715,33.02 149.225,33.02 150.241,33.02 151.257,33.02 152.273,33.02 2.667,34.036 3.683,34.036 4.699,34.036 5.715,34.036 149.225,34.036 150.241,34.036 151.257,34.036 152.273,34.036 2.667,35.052 3.683,35.052 4.699,35.052 5.715,35.052 149.225,35.052 150.241,35.052 151.257,35.052 152.273,35.052 2.667,36.068 3.683,36.068 4.699,36.068 5.715,36.068 20.098,36.068 134.842,36.068 149.225,36.068 150.241,36.068 151.257,36.068 152.273,36.068 2.667,37.084 3.683,37.084 4.699,37.084 5.715,37.084 20.098,37.084 134.842,37.084 149.225,37.084 150.241,37.084 151.257,37.084 152.273,37.084 2.667,38.1 3.683,38.1 4.699,38.1 5.715,38.1 18.066,38.1 19.082,38.1 20.098,38.1 134.842,38.1 135.858,38.1 136.874,38.1 149.225,38.1 150.241,38.1 151.257,38.1 152.273,38.1
HB1: C13.2 U1.9 | length 3.8
  Top Layer w0.343: U1.9@67.172,43.289 U1.9@67.547,43.289 ; U1.9@67.635,43.286 69.741,41.179 69.741,41.036 69.824,40.953 C13.2@70.014,40.953
HB2: C14.1 U1.16 | length 3.8
  Top Layer w0.343: U1.16@67.183,46.888 67.613,46.888 C14.1@69.981,49.256
HO1: R21.2 R25.2 U1.8 | length 37.1
  Top Layer w0.254: U1.8@66.749,42.685 66.749,42.64 66.751,42.638 66.951,42.638 v1(66.999,42.591)
  Top Layer w0.356: U1.8@66.75,42.529 U1.8@66.75,42.834
  Top Layer w0.508: R21.2@82.582,31.126 v1(83.179,31.126) ; R25.2@83.013,21.738 83.179,21.903 v1(83.179,22.227)
  Signal Layer 4 w0.61: v1(66.999,42.591) 67.766,42.591 69.904,40.452 73.002,37.354 73.002,33.515 76.332,30.186 81.558,30.186 81.915,29.829 81.915,27.031 82.272,26.674 82.571,26.674 ; v1(83.179,22.227) 83.179,26.218 82.719,26.678 83.179,27.138 v1(83.179,31.126)
HO2: R23.1 R27.1 U1.17 | length 38.1
  Top Layer w0.254: U1.17@66.747,47.486 66.747,47.541 U1.17@66.749,47.543
  Top Layer w0.356: U1.17@66.749,47.333 U1.17@66.749,47.637
  Top Layer w0.508: R23.1@82.525,52.744 v1(83.121,52.744) ; R27.1@82.525,61.605 82.525,61.582 83.091,61.582 v1(83.11,61.563)
  Signal Layer 4 w0.61: v1(66.994,47.543) 67.802,47.543 71.1,50.841 72.898,52.639 72.898,58.466 75.109,60.677 81.309,60.677 81.915,60.071 81.915,57.561 82.272,57.204 82.55,57.204 ; v1(83.121,52.744) 83.121,56.784 82.698,57.207 83.145,57.655 v1@83.145,61.638
ILIM/IMON: J9.19 J10.19 R7.2 R8.2 U1.31 | length 92
  Top Layer w0.254: R7.2@58.734,44.689 58.734,43.89 R8.2@58.982,43.642 ; R8.2@58.982,43.621 59.131,43.494 59.216,43.41 v1(61.048,43.41) ; v1@60.992,43.353 61.116,43.478 61.682,43.478 62.037,43.833 U1.31@62.426,43.833
  Signal Layer 4 w0.254: J10.19@19.05,90.678 19.05,93.336 20.318,94.604 20.318,96.603 19.457,97.464 19.457,97.47 19.05,97.877 J9.19@19.05,98.255 ; v1(41.701,83) 45.072,83 46.132,81.939 46.132,74.443 50.579,69.997 50.579,57.409 52.252,55.736 52.252,53.546 58.264,47.534 58.264,44.396 59.574,43.086 60.702,43.086 60.761,43.145 61.026,43.41 v1(61.048,43.41)
  Bottom Layer w0.254: J10.19@19.05,90.678 19.05,90.345 20.36,89.035 20.36,86.406 22.766,84 32.368,84 33.368,83 v1(41.701,83)
L1: L1.2 R11.1 R12.1 | length 15.2
  Bottom Layer w0.254: v4(58.471,10.414) 58.801,10.084 60.518,10.084 60.517,10.09
  Bottom Layer w1.016: 60.517,10.09 cw(c58.471,10.414) 60.524,10.137
L2: L2.1 R13.2 R14.2 | length 15.1
  Bottom Layer w0.254: v4(58.471,79.248) 58.748,78.971 60.524,78.971
  Bottom Layer w1.016: 60.517,78.924 cw(c58.471,79.248) 60.524,78.971
LO1: R22.1 R26.1 U1.11 | length 46.5
  Top Layer w0.254: R26.1@74.186,22.227 R26.1@74.3,22.114 ; R22.1@74.187,31.126 R22.1@74.301,31.012
  Top Layer w0.343: U1.11@67.199,44.284 67.399,44.284 68.327,44.284 v1(69.26,43.352)
  Top Layer w0.559: v1(73.845,31.126) R22.1@74.187,31.126 ; v1@73.854,22.218 v1(73.844,22.227) R26.1@74.186,22.227
  Signal Layer 1 w0.61: v1(69.26,43.352) 71.247,43.352 72.541,43.352 73.025,42.868 73.025,36.904 71.374,35.253 71.374,27.178 ; 71.374,27.178 71.847,26.705 ; 71.374,27.178 71.847,26.705 ; 71.847,26.705 72.435,26.705 ; 71.847,26.705 72.435,26.705 ; 72.435,26.705 73.031,27.301 ; 72.435,26.705 73.031,26.109 ; 72.435,26.705 73.031,26.109 ; 72.435,26.705 73.031,27.301 ; 73.031,23.04 v1(73.844,22.227) 73.031,23.04 ; 73.031,23.04 73.031,26.109 ; 73.031,23.04 73.031,26.109 ; 73.031,27.301 73.031,30.328 ; 73.031,27.301 73.031,30.328 ; 73.031,30.328 73.837,31.134 73.031,30.328
LO2: R24.2 R28.2 U1.14 | length 37.8
  Top Layer w0.254: R28.2@74.18,61.628 R28.2@74.294,61.514 ; R24.2@74.186,52.707 R24.2@74.3,52.594
  Top Layer w0.343: U1.14@67.199,45.886 67.399,45.886 68.288,45.886 69.226,46.824 v1(69.266,46.824)
  Top Layer w0.559: v1(73.838,61.628) R28.2@74.18,61.628 ; v1(73.844,52.707) R24.2@74.186,52.707
  Signal Layer 1 w0.61: v1(69.266,46.824) 70.442,46.824 71.247,47.629 71.247,56.769 ; 71.247,56.769 71.628,57.15 ; 71.247,56.769 71.628,57.15 ; 71.628,57.15 72.429,57.15 ; 71.628,57.15 72.429,57.15 ; 72.429,57.15 73.025,57.746 ; 72.429,57.15 73.025,56.554 ; 72.429,57.15 73.025,56.554 ; 72.429,57.15 73.025,57.746 ; 73.025,53.527 73.025,56.554 ; 73.025,53.527 v1(73.844,52.707) 73.025,53.527 ; 73.025,53.527 73.025,56.554 ; 73.025,57.746 73.025,60.815 ; 73.025,57.746 73.025,60.815 ; 73.025,60.815 v1(73.838,61.628) 73.025,60.815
